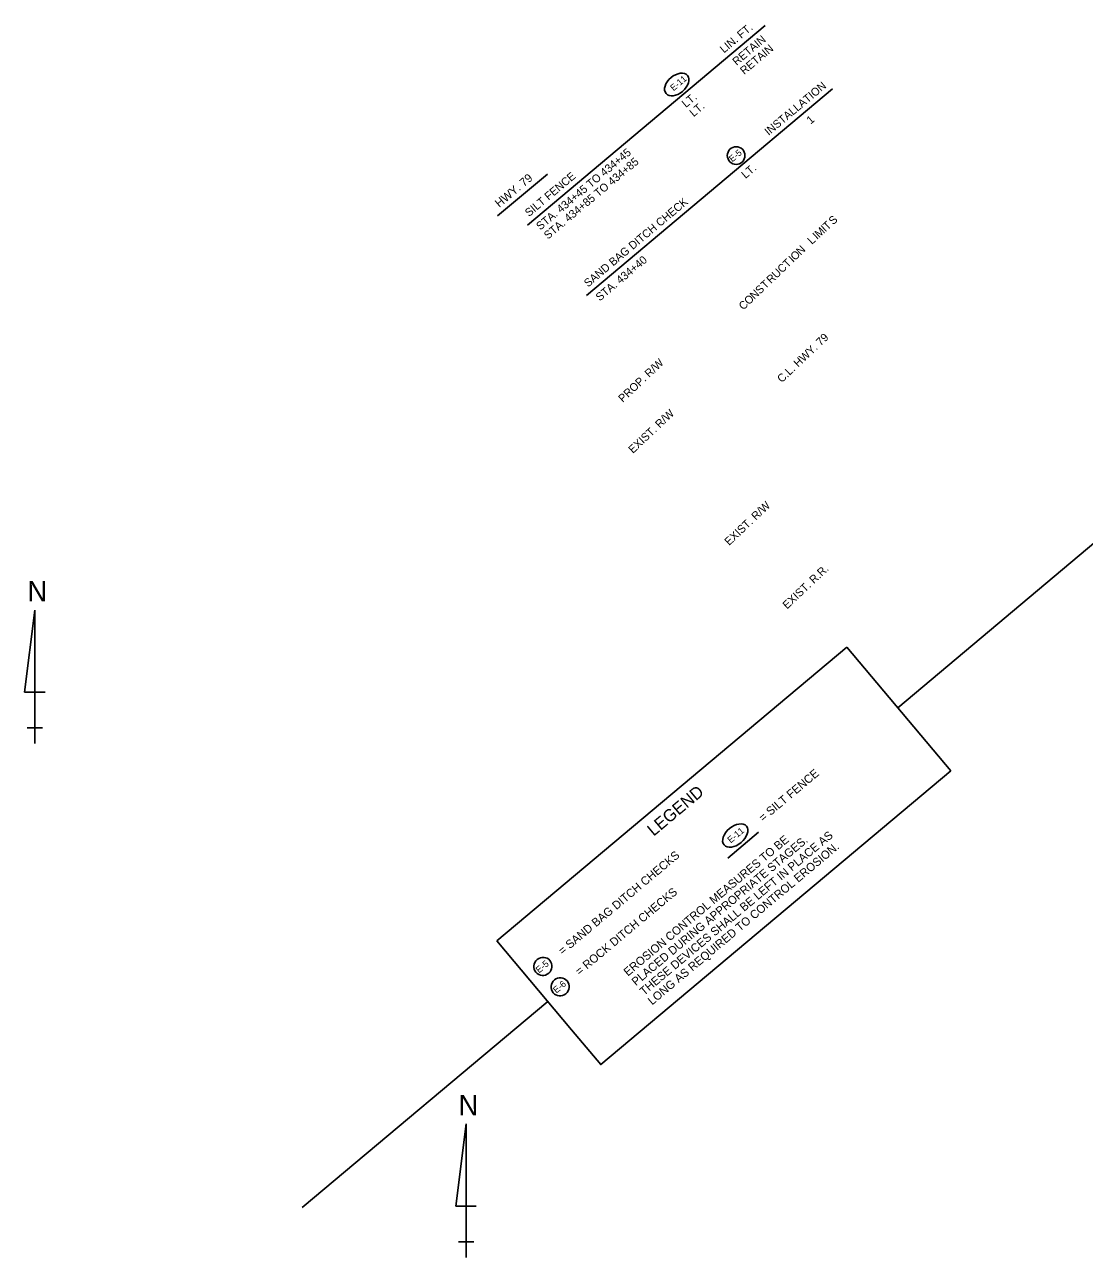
# Model space of a CAD drawing. Extents: x 1430270 to 1431940, y 1964864 to 1966264.
# Drawn here: x 1430270 to 1431064, y 1964864 to 1965788 of the extents above; entities that cross this region are included whole.
import ezdxf

# ---------------------------------------------------------------- set-up
doc = ezdxf.new("R2010")
doc.units = 0
for name, color, linetype in [('1', 7, 'Continuous'), ('44', 7, 'Continuous'), ('63', 7, 'Continuous'), ('Level 1', 7, 'Continuous'), ('Level 44', 7, 'Continuous'), ('R_Draft', 7, 'Continuous')]:
    doc.layers.add(name, color=color, linetype=linetype)

msp = doc.modelspace()

# ---------------------------------------------------------------- linework, layer by layer
at = {"layer": '1'}
for p, q in [((1430924.55, 1965276.13), (1431143.78, 1965460.09)), ((1430623.95, 1965101.3), (1430886.44, 1965321.55)), ((1430964.25, 1965228.82), (1430886.44, 1965321.55)), ((1430679.95, 1965034.55), (1430623.95, 1965101.3)), ((1430477.81, 1964901.27), (1430662.06, 1965055.88))]:
    msp.add_line(p, q, dxfattribs=at)
msp.add_lwpolyline([(1430679.95, 1965034.55), (1430701.76, 1965008.57), (1430964.25, 1965228.82)], dxfattribs=at)
msp.add_circle((1430803.32, 1965690.19), 6.61, dxfattribs=at)
msp.add_ellipse((1430758.79, 1965743.46), major_axis=(8.06, 6.76), ratio=0.638788, dxfattribs=at)
at = {"layer": '44'}
for p, q in [((1430646.71, 1965638.03), (1430825.04, 1965787.67)), ((1430691.02, 1965585.22), (1430875.64, 1965740.14)), ((1430624.4, 1965644.89), (1430661.81, 1965676.28))]:
    msp.add_line(p, q, dxfattribs=at)
at = {"layer": '63'}
for p, q in [((1430277.36, 1965349.41), (1430269.66, 1965287.87)), ((1430277.36, 1965249.41), (1430277.36, 1965349.41)), ((1430277.36, 1965349.41), (1430277.36, 1965272.49)), ((1430269.66, 1965287.87), (1430285.05, 1965287.87)), ((1430277.36, 1965249.41), (1430277.36, 1965272.49)), ((1430277.36, 1965260.95), (1430271.59, 1965260.95)), ((1430271.59, 1965260.95), (1430283.13, 1965260.95)), ((1430277.36, 1965249.41), (1430277.36, 1965260.95)), ((1430600.76, 1964963.99), (1430593.06, 1964902.46)), ((1430600.76, 1964863.99), (1430600.76, 1964963.99)), ((1430600.76, 1964963.99), (1430600.76, 1964887.07)), ((1430593.06, 1964902.46), (1430608.45, 1964902.46)), ((1430600.76, 1964863.99), (1430600.76, 1964887.07)), ((1430600.76, 1964875.53), (1430594.99, 1964875.53)), ((1430594.99, 1964875.53), (1430606.53, 1964875.53)), ((1430600.76, 1964863.99), (1430600.76, 1964875.53))]:
    msp.add_line(p, q, dxfattribs=at)
at = {"layer": 'Level 1'}
for centre, major_axis, ratio in [((1430802.63, 1965180.25), (8.39, 7.04), 0.622952), ((1430658.42, 1965082.15), (-5.27, -4.42), 0.97521), ((1430671.28, 1965066.83), (-5.27, -4.42), 0.97521)]:
    msp.add_ellipse(centre, major_axis=major_axis, ratio=ratio, dxfattribs=at)
at = {"layer": 'Level 44'}
msp.add_lwpolyline([(1430797.09, 1965163.42), (1430820.16, 1965182.79)], dxfattribs=at)

# ---------------------------------------------------------------- texts
at = {"layer": '1'}
for s, rotation, p in [('E-11', 39.99998, (1430756.33, 1965738.31)), ('E-5 ', 40, (1430800.45, 1965685.06))]:
    msp.add_text(s, height=4.8, rotation=rotation, dxfattribs=at).set_placement(p)
at = {"layer": '44'}
for s, height, rotation, p in [('LIN. FT.', 6, 39.99998, (1430794.17, 1965766.67)), ('RETAIN', 6, 39.99998, (1430803.64, 1965757.41)), ('RETAIN', 6, 39.99998, (1430809.39, 1965750.56)), ('INSTALLATION', 6, 40, (1430827.76, 1965704.86)), ('LT.', 6, 39.99998, (1430765.65, 1965725.75)), ('LT.', 6, 39.99998, (1430771.41, 1965718.9)), ('1', 6, 40, (1430859.2, 1965713.37)), ('STA. 434+45 TO 434+45', 6, 39.99998, (1430656.42, 1965633.91)), ('STA. 434+85 TO 434+85', 6, 39.99998, (1430662.18, 1965627.05)), ('HWY. 79', 6.25, 40, (1430625.68, 1965650.9)), ('SILT FENCE      ', 6, 39.99998, (1430647.97, 1965643.99)), ('LT.', 6, 40, (1430810.3, 1965672.55)), ('SAND BAG DITCH CHECK', 6, 40, (1430692.28, 1965591.18)), ('STA. 434+40', 6, 40, (1430701.07, 1965580.71))]:
    msp.add_text(s, height=height, rotation=rotation, dxfattribs=at).set_placement(p)
at = {"layer": '63'}
for p in [(1430271.72, 1965355.82), (1430595.12, 1964970.4)]:
    msp.add_text('N', height=15.38, rotation=360, dxfattribs=at).set_placement(p)
at = {"layer": 'Level 1'}
for s, height, p in [('= SILT FENCE', 6.25, (1430823.53, 1965190.25)), ('E-11 ', 4.876, (1430799.27, 1965174.31)), ('EROSION CONTROL MEASURES TO BE', 6.25, (1430722.15, 1965074.45)), ('PLACED DURING APPROPRIATE STAGES. ', 6.25, (1430728.2, 1965067.24)), ('THESE DEVICES SHALL BE LEFT IN PLACE AS ', 6.25, (1430734.25, 1965060.03)), ('= SAND BAG DITCH CHECKS', 6.25, (1430673.09, 1965090.38)), ('LONG AS REQUIRED TO CONTROL EROSION.', 6.25, (1430740.3, 1965052.83)), ('= ROCK DITCH CHECKS', 6.25, (1430685.95, 1965075.06)), ('E-5 ', 4.876, (1430655.53, 1965076.83)), ('E-6 ', 4.876, (1430668.49, 1965061.71))]:
    msp.add_text(s, height=height, rotation=40.00001, dxfattribs=at).set_placement(p)
at = {"layer": 'Level 44'}
msp.add_text('LEGEND', height=9.143, rotation=40.00001, dxfattribs=at).set_placement((1430741.39, 1965179.35))
at = {"layer": 'R_Draft'}
for s, rotation, p in [('I', 42.52199, (1430870.25, 1965632.55)), ('T', 42.52199, (1430871.71, 1965633.89)), ('S', 42.52199, (1430876.03, 1965637.85)), ('I', 42.7757, (1430864.08, 1965626.84)), ('M', 42.7757, (1430865.53, 1965628.18)), ('N', 43.84149, (1430851.69, 1965615.11)), ('L', 43.11957, (1430860.15, 1965623.15)), ('T', 43.83733, (1430841.81, 1965605.62)), ('I', 43.83733, (1430846.03, 1965609.68)), ('O', 43.83733, (1430847.46, 1965611.06)), ('R', 43.70937, (1430829.47, 1965593.78)), ('U', 43.91643, (1430833.57, 1965597.69)), ('C', 43.91643, (1430837.72, 1965601.69)), ('S', 43.74635, (1430821.14, 1965585.81)), ('T', 43.74635, (1430825.24, 1965589.73)), ('O', 43.68624, (1430812.8, 1965577.85)), ('N', 43.68624, (1430817.04, 1965581.9)), ('C', 43.68104, (1430808.7, 1965573.93)), ('C.L. HWY. 79', 43.42441, (1430837.55, 1965519.46)), ('PROP. R/W', 43.36601, (1430718.35, 1965504.7)), ('EXIST. R/W', 43.36601, (1430725.92, 1965466.42)), ('EXIST. R/W', 43.36601, (1430798.03, 1965397.38)), ('EXIST. R.R.', 43.39194, (1430841.54, 1965349.75))]:
    msp.add_text(s, height=6, rotation=rotation, dxfattribs=at).set_placement(p)

doc.saveas('drawing.dxf')
